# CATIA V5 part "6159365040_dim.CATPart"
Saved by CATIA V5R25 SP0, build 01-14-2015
Part number: 6159365040_dim
Source: made
Property "PROI_CREATED_ON": "12/17/2008 9:21:37 AM"
Property "BLANK_DRAWING": "--"
Property "DRAWN_BY": "--"
Property "FINISH": "--"
Property "HEAT_TREATMENT": "ASSIGN"
Property "MATERIAL": "ASSIGN"
Property "PROJECT": "--"
Property "PROTOTYPE_NO": "--"
Property "RELATED_DRAWING": "--"
Property "COMPLETE_MATERIAL": "ASSIGN-ASSIGN"
Property "DESCRIPTION": "Wrench Protection"
Property "DRAWING_EXIST": "--"
Property "MANUFACTURER": "--"
Property "MANUFACTURER_2": "--"
Property "MANUFACTURER_REF": "--"
Property "TYPE_PART": "--"
Property "TODAY_DATE": "YY/MM/DD"
Property "MFG_WP_MATERIAL": "ASSIGN"
Property "COMPANY_CODE": "---"
Property "DESCRIPTION_JP": "--"
Property "PQP_DOCUMENT": "--"
Property "PTC_VAL_IMP_PART_STATUS": "OK"
Property "PTC_MP_VAL_IMP_VOLUME": 8.37758e-09 (volume)
Property "PTC_MP_VAL_IMP_AREA": 2.51327e-05 (area)
Property "PTC_MP_VAL_IMP_COGX": 29.2698 mm
Property "PTC_MP_VAL_IMP_COGY": 67.5574 mm
Property "PTC_MP_VAL_IMP_COGZ": 41.6523 mm
Property "PTC_VAL_IMP_SCORE": "PASS"
Property "PTC_MP_IMP_VOLUME": 8.37758
Property "PTC_MP_IMP_AREA": 55607.7
Property "PTC_MP_IMP_COGX": 29.2698
Property "PTC_MP_IMP_COGY": 67.5574
Property "PTC_MP_IMP_COGZ": 41.6523
Property "PTC_MODIFIED": false
Property "PDMREV": "01.0"
Property "PDMRL": "Production"
Property "PROI_REVISION": "01"
Property "PROI_VERSION": "0"
Property "PROI_RELEASE": "Production"
Property "PTC_WM_ITERATION": "0"
Property "PTC_WM_VERSION": "01.0"
Property "PTC_WM_CREATED_ON": "26-May-21 11:50:14 AM"
Property "PTC_WM_MODIFIED_ON": "26-May-21 11:51:29 AM"
Property "PTC_WM_NAME": "6159365040_dim.prt"
Property "PTC_WM_NUMBER": "6159365040_DIM.PRT"
Property "PTC_WM_LIFECYCLE_STATE": "Production"
Property "PTC_WM_LIFECYCLE": "Design_Process"
Property "PTC_WM_REVISION": "01"
Property "PTC_WM_CREATED_BY": "Administrateur Organisation CPD (INTRALINK: CPD)"
Property "PTC_WM_MODIFIED_BY": "Administrateur Organisation CPD (INTRALINK: CPD)"
Property "PTC_ORGANIZATION_ID": "CPD"
Property "PTC_WM_LOCATION": "/Products/TORQUE MEASUREMENT SYSTEMS/A1670 - TORQUE WRENCH DELTA WRENCH/9-01-Dim"
Property "PTC_WM_TEAM": "Default"
Property "EXPORT_CONTROL": "NULL"
Property "PTC_COMMON_NAME": "6159365040_dim.prt"
Property "PTC_MASTER_MATERIAL": "ASSIGN"
Material "ASSIGN": density 1000 kg/m3, Young's modulus 1e+07 Pa, thermal expansion 1e-05 1/K
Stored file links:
  d:\ptc\Echange\temp\6159365040_dim.CATPart

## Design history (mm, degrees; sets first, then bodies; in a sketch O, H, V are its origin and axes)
AxisSystem1 "CS0": origin (0, 0, 0), X (1, 0, 0), Y (0, 1, 0), Z (0, 0, 1)
AxisSystem2 "6159365040": origin (0, 0, 0), X (1, 0, 0), Y (0, 1, 0), Z (0, 0, 1)
Set1
  DatumSurface1 "Sheet.1"
  Plane1 "RIGHT": stored without definition
  Plane2 "TOP": stored without definition
  Plane3 "FRONT": stored without definition
Body1 "PartBody" (main body), material "ASSIGN"
  Solid1 "Solid.1": solid without history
